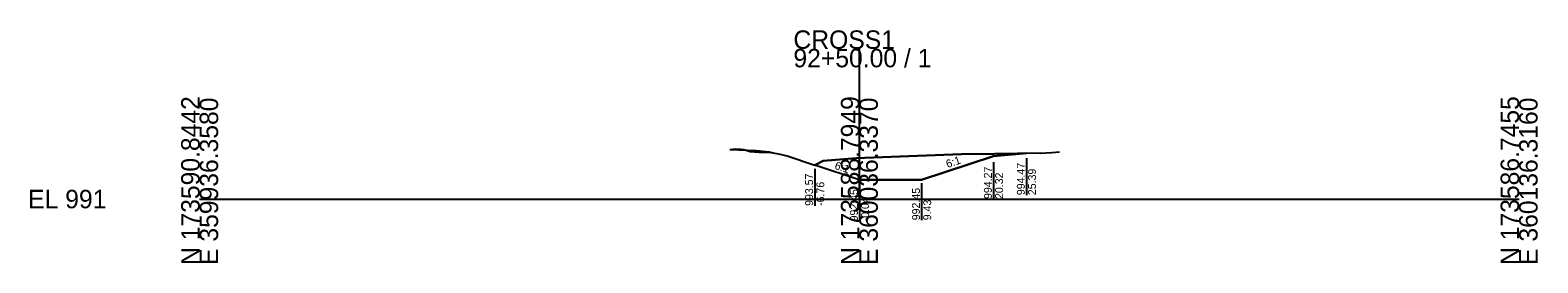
# Model space of a CAD drawing. Extents: x -26 to 1403, y -10 to 11027.
# Drawn here: x -25.7 to 202.8, y 7490.3 to 7525.6 of the extents above; entities that cross this region are included whole.
import ezdxf

# ---------------------------------------------------------------- set-up
doc = ezdxf.new("R2010")
doc.units = 0
for name, color, linetype in [('Default', 7, 'Continuous'), ('P_E_XS_Ground', 7, 'Continuous'), ('P_XS', 7, 'Continuous'), ('P_XS_EAR_CommonGrnd', 7, 'Continuous'), ('P_XS_Lane', 7, 'Continuous'), ('P_XS_Rock', 7, 'Continuous')]:
    doc.layers.add(name, color=color, linetype=linetype)

msp = doc.modelspace()

# ---------------------------------------------------------------- linework, layer by layer
at = {"layer": 'Default'}
for p, q in [((100, 7500), (100, 7522.8)), ((0, 7500), (100, 7500)), ((100, 7500), (200, 7500))]:
    msp.add_line(p, q, dxfattribs=at)
at = {"layer": 'P_E_XS_Ground'}
for p, q in [((80.34, 7507.51), (81.26, 7507.6)), ((81.26, 7507.6), (82.01, 7507.59)), ((82.01, 7507.59), (82.48, 7507.52)), ((82.48, 7507.52), (83.43, 7507.23)), ((83.43, 7507.23), (84.74, 7507.13)), ((84.74, 7507.13), (86.6, 7507.06)), ((86.6, 7507.06), (87.76, 7506.85)), ((87.76, 7506.85), (89.05, 7506.56)), ((89.05, 7506.56), (93.08, 7505.19)), ((93.08, 7505.19), (93.24, 7505.14)), ((94.5, 7505.78), (93.24, 7505.14)), ((99.5, 7506.18), (94.5, 7505.78)), ((115.5, 7506.82), (99.5, 7506.18)), ((120.5, 7506.88), (115.5, 7506.82)), ((127.44, 7506.96), (120.5, 7506.88)), ((127.44, 7506.96), (129.18, 7507.08)), ((129.18, 7507.08), (130.33, 7507.17))]:
    msp.add_line(p, q, dxfattribs=at)
at = {"layer": 'P_XS'}
for p, q in [((80.34, 7507.51), (84.34, 7507.35)), ((84.34, 7507.35), (86.34, 7507.19)), ((86.34, 7507.19), (86.93, 7507))]:
    msp.add_line(p, q, dxfattribs=at)
at = {"layer": 'P_XS_EAR_CommonGrnd'}
msp.add_lwpolyline([(99.96, 7502.9), (93.24, 7505.14), (94.5, 7505.78), (99.5, 7506.18), (115.5, 7506.82), (120.5, 7506.88), (125.39, 7506.94), (120.32, 7506.53), (109.43, 7502.9)], close=True, dxfattribs=at)
at = {"layer": 'P_XS_Lane'}
for p, q in [((99.96, 7502.9), (93.24, 7505.14)), ((109.43, 7502.9), (120.32, 7506.53)), ((120.32, 7506.53), (125.39, 7506.94)), ((99.96, 7502.9), (109.43, 7502.9))]:
    msp.add_line(p, q, dxfattribs=at)
at = {"layer": 'P_XS_Rock'}
for p, q in [((120.33, 7505.62), (120.33, 7500.01)), ((125.32, 7506.21), (125.32, 7500.59)), ((93.23, 7504.58), (93.23, 7498.96)), ((100.02, 7502.22), (100.02, 7496.61)), ((109.43, 7502.39), (109.43, 7496.78))]:
    msp.add_line(p, q, dxfattribs=at)

# ---------------------------------------------------------------- texts
at = {"layer": 'Default'}
for s, p in [('CROSS1', (90, 7522.8)), ('92+50.00 / 1', (90, 7520)), ('EL 991', (-26, 7498.6))]:
    msp.add_text(s, height=2.8, dxfattribs=at).set_placement(p)
for s, p in [('N 173590.8442', (0, 7490)), ('E 359936.3580', (2.8, 7490)), ('N 173588.7949', (100, 7490)), ('E 360036.3370', (102.8, 7490)), ('N 173586.7455', (200, 7490)), ('E 360136.3160', (202.8, 7490))]:
    msp.add_text(s, height=2.8, rotation=90, dxfattribs=at).set_placement(p)
at = {"layer": 'P_XS_Rock'}
for s, rotation, p in [('6:1', 341.5651, (96.15, 7504.61)), ('6:1', 18.4349, (113.36, 7504.71)), ('994.47', 90, (125.07, 7500.59)), ('993.57', 90, (92.98, 7498.96)), ('994.27', 90, (120.08, 7500.01)), ('20.32', 90, (121.78, 7500.01)), ('25.39', 90, (126.77, 7500.59)), ('-6.76', 90, (94.68, 7498.96)), ('992.45', 90, (99.77, 7496.61)), ('992.45', 90, (109.18, 7496.78)), ('-0.04', 90, (101.47, 7496.61)), ('9.43', 90, (110.88, 7496.78))]:
    msp.add_text(s, height=1.2, rotation=rotation, dxfattribs=at).set_placement(p)

doc.saveas('drawing.dxf')
